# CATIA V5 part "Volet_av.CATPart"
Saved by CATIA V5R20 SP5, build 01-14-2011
Part number: Skl_Volet_av
Publications: "Axe_pivot_vol_av/gouv", "Axe_glissiere_vol_av/bras_av", "Plan_glissiere_vol_av/bras_av"
Bounding box of the stored display mesh (mm): x 0 to 0, y 360 to 450, z -1010 to -10
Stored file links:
  U:\2A\CFAO\dossier sans titre\Volet_av.CATPart
  U:\2A\CFAO\dossier sans titre\Skl_gouvernail.CATProduct
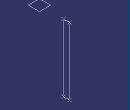
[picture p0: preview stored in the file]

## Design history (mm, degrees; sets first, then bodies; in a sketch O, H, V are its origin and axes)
Set1
  Point1 to Point4: linked copy from another document
  Plane1 "Plan_xy-10mm": linked copy from another document
Body1 (main body)
  Line1: type PtPt, FirstPoint Point1, SecondPoint Point2
  Line2 "Axe_pivot_vol_av/gouv": type PtPt, FirstPoint Point3, SecondPoint Point4
  Line3: type PtPt, FirstPoint Point3, SecondPoint Point1
  Line4 "Axe_glissiere_vol_av/bras_av": type PtPt, FirstPoint Point4, SecondPoint Point2
  Plane2 "Plan_glissiere_vol_av/bras_av": type Offset, RefPlane Plane1, Offset 0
